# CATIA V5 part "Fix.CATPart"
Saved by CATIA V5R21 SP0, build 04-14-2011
Part number: Part1
Bounding box of the stored display mesh (mm): x -20 to 0, y -45 to 45, z -45 to 45
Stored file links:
  D:\CATIA V5R21 E-RESOURCES\CATIA-V5R21\catia-v5r21-prt\c16-catia-v5r20-prt\Cable Joint - (Fig16-60)\CAT_V5R21_Fix.CATPart
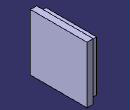
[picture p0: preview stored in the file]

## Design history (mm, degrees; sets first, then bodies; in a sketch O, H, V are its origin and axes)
Body1 (main body)
  Sketch1 on yz-plane, origin (0, 0, 0), H (0, 1, 0), V (0, 0, 1)
    line L1 (40, 40) -> (40, -40)
    line L2 (40, -40) -> (-40, -40)
    line L3 (-40, -40) -> (-40, 40)
    line L4 (-40, 40) -> (40, 40)
    line L5 (45, 45) -> (45, -45)
    line L6 (45, -45) -> (-45, -45)
    line L7 (-45, -45) -> (-45, 45)
    line L8 (-45, 45) -> (45, 45)
    length L4 = 80
    length L1 = 80
    length L5 = 90
    length L8 = 90
    vertical: L1 V, L3 V, L5 V, L7 V
    horizontal: L2 H, L4 H, L6 H, L8 H
    equidistance: L1 L3 O, L2 L4 O, L5 L7 O, L6 L8 O
  MultiPad1: profile Sketch1, domains (length 10; length 20)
